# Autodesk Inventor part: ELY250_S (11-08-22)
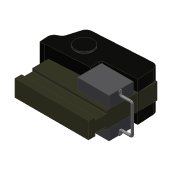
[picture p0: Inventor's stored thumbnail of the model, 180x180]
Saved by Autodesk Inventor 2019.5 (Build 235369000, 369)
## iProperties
Created: 2022-08
Part Number: ELY250_S (11-08-22)
Material: St37-2 / S235
Document SubType Name: Modeling
Designer: schoth
Density: 7.86 g/cm^3
Appearance: Steel
RuleStatus: InUse
Author: schoth
Mass(KG): 0.0
Area(mm): 0.0
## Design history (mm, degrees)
derived "ELY250.iam"
body "Solid1"
node "FB225-005.ipt:1"
node "ELY250-88.iam:1::FB229-030.ipt:1"
node "ELY250-88.iam:1::FB603-070.ipt:1"
node "ELY250-99.iam:1::FB226-011.ipt:1"
node "ELY250-99.iam:1::FB227-104.ipt:1"
node "ELY250.iam_Bodies"
